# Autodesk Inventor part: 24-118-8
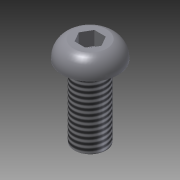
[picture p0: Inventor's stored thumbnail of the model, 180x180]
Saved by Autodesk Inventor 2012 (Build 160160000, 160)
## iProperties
Created: 2004-10
Part Number: 24-118-8
Material: Steel, High Strength Low Alloy
Document SubType Name: Modeling
Designer: Autodesk, Inc.
Manufacturer: Standard
Standards Organization: Custom
Description: SCREW, PARKER IPS, BUTTON HEAD, M8X18
Catalog Web Link: http://www.parker.com/ead/cm1.asp?cmid=809
Vendor: PARKER IPS
Mass: 10.8823 g
Surface Area: 9.37524 cm^2
Volume: 1.38805 cm^3
Density: 7.84 g/cm^3
CAGE: 1LJX3
Dept. ID: Product Design
Description #2: ---
Finish #1: ---
Finish #2: ---
Material ID: ---
Project Number: ---
Author: Autodesk, Inc.
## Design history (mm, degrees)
sketch "Sketch1"
  geometry: C1 r 4 at (0, 0); 1 further point
  constraints: 1 centre point, 1 coincident
  dimensions: "Dia" = 8 diameter of C1
extrude "Base" new body sketch "Sketch1" taper "d2" = 0 deg; distance "Length" = 18
node "Hex Key Sketch Plane"
sketch "Sketch2"
  geometry: L1 (0, -0.969)-(0, 5.814) reference; L2 (-4, 0)-(4, 0) reference; L3 (0, 0)-(7, 0); L4 (7, 0)-(7, 0.44); L5 (4.2, 4.4)-(0, 4.4); L6 (0, 4.4)-(0, 0); A1 r 4.2 centre (2.8, 0.44) between (7, 0.44) and (4.2, 4.4)
  constraints: 8 end point, 2 collinear, 2 perpendicular, 2 point on circle, 1 centre point, 1 midpoint, 1 point on line, 1 tangent
  dimensions: "d3" = 4.4 distance between parallel lines of L3 L5 (= H_K); "d4" = 0.44 distance of L3.end L4.end (= 0.1 x H_K); "d5" = 14 diameter of L4 L1 (= Dk); "d6" = 2.8 distance from line of L4 L5.start (= 0.2 x Dk)
revolve "Button Head" sketch "Sketch2" stored, may be unused: angle "d7" = 90 deg
sketch "Sketch4"
  geometry: L1 (0, -0.88)-(0, 5.28) reference; L2 (-4, 0)-(4, 0) reference; L3 (0, 0)-(7, 0); L4 (7, 0)-(7, 4.4); L5 (7, 4.4)-(0, 4.4); L6 (0, 4.4)-(0, 0)
  constraints: 8 end point, 2 parallel, 1 horizontal, 1 midpoint, 1 perpendicular
  dimensions: "d13" = 4.4 distance of L3.end L4.end (= H_K); "d14" = 14 diameter of L4 L1 (= Dk)
revolve "Cap Head" sketch "Sketch4" stored, may be unused: angle "d15" = 90 deg
sketch "Sketch3"
  geometry: L1 (0, -21.6)-(0, 3.6) reference; L2 (-4, 0)-(4, 0) reference; L3 (4, 0)-(4, -18) reference; L4 (0, 0)-(7, 0); L5 (7, 0)-(7, -0.44); L6 (7, -0.44)-(4, -4.4); L7 (4, -4.4)-(0, -4.4); L8 (0, 0)-(0, -4.4)
  constraints: 10 end point, 3 point on line, 2 perpendicular, 1 collinear, 1 midpoint
  dimensions: "d9" = 4.4 distance between parallel lines of L7 L4 (= H_K); "d10" = 14 diameter of L5 L1 (= Dk); "d11" = 0.44 distance of L4.end L5.end (= 0.1 x H_K)
revolve "Flat Head" sketch "Sketch3" stored, may be unused: angle "d12" = 90 deg
sketch "Sketch5"
  geometry: L1 (1.443, 2.5)-(2.887, 0); L2 (2.887, 0)-(1.443, -2.5); L3 (1.443, -2.5)-(-1.443, -2.5); L4 (-1.443, -2.5)-(-2.887, 0); L5 (-2.887, 0)-(-1.443, 2.5); L6 (-1.443, 2.5)-(1.443, 2.5); 2 further points
  constraints: 12 end point, 1 coincident, 1 horizontal, 11 other
  dimensions: "d16" = 5 distance between parallel lines of L3 L6 (= H_S)
extrude "Hex Socket" cut sketch "Sketch5" distance "d17" = 3.52 (= 0.8 x H_K); taper "d18" = 0 deg
thread "Thread1" dims "d19" = 10, "d20" = 0
body "Solid1"
other parameters: "Dk" = 14 [user parameter; used in 4 equation terms], "H_K" = 4.4 [user parameter; used in 7 equation terms], "H_S" = 5 [user parameter; used in 1 equation term], "HexStartHeight" = 4.4 (= H_K)
